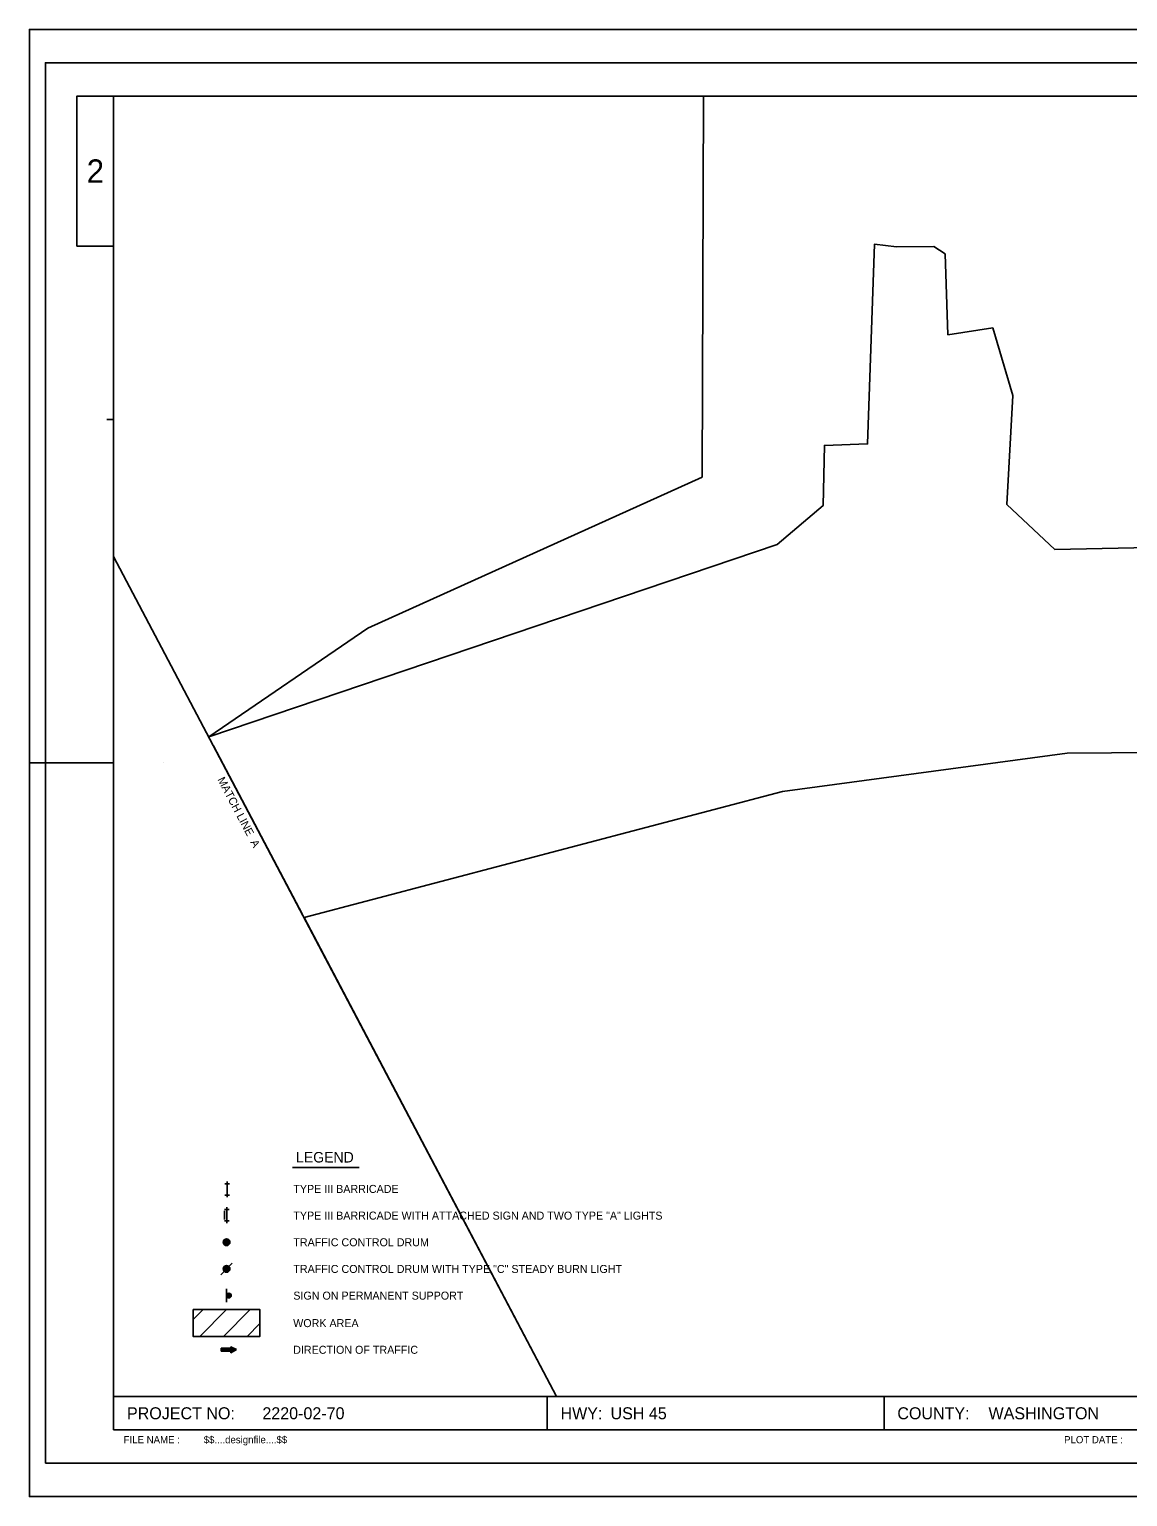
# Model space of a CAD drawing. Extents: x 359903 to 361603, y 132699 to 133799.
# Drawn here: x 359903 to 360726, y 132699 to 133799 of the extents above; entities that cross this region are included whole.
import ezdxf

# ---------------------------------------------------------------- set-up
doc = ezdxf.new("R2010")
doc.units = 0
for name, color, linetype in [('CA-MTCH-LINE', 7, 'Continuous'), ('CA-MTCH-LINE-TEXT', 7, 'Continuous'), ('Default', 7, 'Continuous'), ('P_Kapur_PFFE CELL [KAPUR_CADDS_LEVELS]', 7, 'Continuous'), ('P_RDWY_Text', 7, 'Continuous'), ('P_TC', 7, 'Continuous'), ('P_TC_FlowArrow', 7, 'Continuous'), ('P_TC_Text', 7, 'Continuous'), ('PLT_Sheet_Border', 7, 'Continuous'), ('PLT_Sheet_Info', 7, 'Continuous')]:
    doc.layers.add(name, color=color, linetype=linetype)

msp = doc.modelspace()

# ---------------------------------------------------------------- linework, layer by layer
at = {"layer": 'CA-MTCH-LINE'}
msp.add_line((360041.1, 133262.2), (360107.9, 133135.6), dxfattribs=at)
at = {"layer": 'Default'}
msp.add_lwpolyline([(361541.3, 132774.3), (360298.3, 132774.3), (359966.3, 133404.1), (359966.3, 133749.3), (361541.3, 133749.3)], close=True, dxfattribs=at)
for points in [[(361039, 133417.1), (360671.8, 133409.4), (360635.9, 133443.1), (360640.4, 133524.8), (360625.3, 133575.4), (360591.7, 133570.4), (360589.6, 133630.9), (360581.1, 133636.4), (360553.1, 133636.3), (360536.8, 133638.3), (360531.5, 133488.5), (360499.1, 133487.4), (360498.1, 133442.3), (360463.6, 133413.1), (360037.7, 133268.8), (360156.9, 133350.4), (360407.4, 133463.6), (360408.4, 133749.3), (361541.3, 133749.3)], [(361541.3, 132774.3), (360298.3, 132774.3), (360109, 133133.5), (360467.7, 133228), (360681.2, 133256.7), (361013.7, 133259.1)]]:
    msp.add_lwpolyline(points, dxfattribs=at)
at = {"layer": 'P_Kapur_PFFE CELL [KAPUR_CADDS_LEVELS]'}
msp.add_lwpolyline([(359903.1, 133799.3), (361603.1, 133799.3), (361603.1, 132699.3), (359903.1, 132699.3), (359903.1, 133799.3)], dxfattribs=at)
at = {"layer": 'P_RDWY_Text'}
msp.add_lwpolyline([(359903.1, 133799.3), (361603.1, 133799.3), (361603.1, 132699.3), (359903.1, 132699.3)], close=True, dxfattribs=at)
at = {"layer": 'P_TC'}
for p, q in [((360051.4, 132933.9), (360051.4, 132935.6)), ((360051.4, 132933.9), (360049.7, 132933.9)), ((360051.4, 132925.4), (360049.7, 132925.4)), ((360051.4, 132925.4), (360051.4, 132933.9)), ((360051.4, 132933.9), (360053.1, 132933.9)), ((360053.1, 132925.4), (360051.4, 132925.4)), ((360051.4, 132925.4), (360051.4, 132923.7)), ((360051.2, 132914.6), (360049.5, 132914.6)), ((360049.5, 132907.1), (360049.5, 132913.6)), ((360051.2, 132914.6), (360051.2, 132916.3)), ((360051.2, 132906.1), (360051.2, 132914.6)), ((360051.2, 132914.6), (360052.9, 132914.6)), ((360051.2, 132906.1), (360049.5, 132906.1)), ((360052.9, 132906.1), (360051.2, 132906.1)), ((360051.2, 132906.1), (360051.2, 132904.4)), ((360046.7, 132865.7), (360055.2, 132874.3)), ((360051, 132845), (360051, 132855)), ((360025.9, 132832.2), (360033.3, 132839.5)), ((360030.9, 132819.4), (360051, 132839.5)), ((360048.6, 132819.4), (360068.6, 132839.5)), ((360066.3, 132819.4), (360075.9, 132829.1))]:
    msp.add_line(p, q, dxfattribs=at)
msp.add_lwpolyline([(360025.9, 132839.5), (360075.9, 132839.5), (360075.9, 132819.4), (360025.9, 132819.4)], close=True, dxfattribs=at)
for centre, radius in [((360051, 132890), 2.5), ((360051, 132890), 2), ((360051, 132890), 1.5), ((360051, 132890), 1), ((360051, 132890), 0.5), ((360051, 132890), 0.25), ((360051, 132870), 2.5), ((360051, 132870), 2), ((360051, 132870), 1.5), ((360051, 132870), 1), ((360051, 132870), 0.5), ((360051, 132870), 0.25), ((360052.7, 132850), 1.75), ((360052.7, 132850), 1), ((360052.7, 132850), 0.25)]:
    msp.add_circle(centre, radius, dxfattribs=at)
at = {"layer": 'P_TC_FlowArrow'}
for p, q in [((360046.9, 132810.5), (360046.9, 132808.3)), ((360046.9, 132810.5), (360054.1, 132810.5)), ((360046.9, 132810.1), (360057.2, 132810.1)), ((360046.9, 132809.6), (360058.1, 132809.6)), ((360046.9, 132809.4), (360046.9, 132809.4)), ((360046.9, 132809.2), (360057.9, 132809.2)), ((360046.9, 132808.7), (360057.1, 132808.7)), ((360046.9, 132808.3), (360054.1, 132808.3)), ((360058.4, 132809.5), (360054.1, 132811.7)), ((360054.1, 132811.7), (360054.1, 132807.2)), ((360054.1, 132811.4), (360054.5, 132811.4)), ((360054.1, 132811), (360055.4, 132811)), ((360054.1, 132810.5), (360056.3, 132810.5)), ((360058.4, 132809.5), (360054.1, 132807.2)), ((360054.1, 132808.3), (360056.2, 132808.3)), ((360054.1, 132807.8), (360055.4, 132807.8)), ((360054.1, 132807.4), (360054.5, 132807.4))]:
    msp.add_line(p, q, dxfattribs=at)
at = {"layer": 'P_TC_Text'}
msp.add_line((360100.4, 132946.1), (360150.3, 132946.1), dxfattribs=at)
at = {"layer": 'PLT_Sheet_Border'}
for points in [[(359903.1, 132699.3), (361603.1, 132699.3), (361603.1, 133799.3), (359903.1, 133799.3)], [(359915.1, 132724.3), (361570.1, 132724.3), (361570.1, 133774.3), (359915.1, 133774.3)]]:
    msp.add_lwpolyline(points, close=True, dxfattribs=at)
at = {"layer": 'PLT_Sheet_Info'}
for p, q in [((359903.1, 133749.3), (359903.1, 133799.3)), ((359903.1, 133799.3), (359953.1, 133799.3)), ((359966.3, 133749.3), (361541.3, 133749.3)), ((359966.3, 132749.3), (359966.3, 133749.3)), ((359966.3, 133506.8), (359961.3, 133506.8)), ((359903.1, 133224.3), (359903.1, 133274.3)), ((359903.1, 133249.3), (359966.3, 133249.3)), ((360003.8, 133249.3), (360003.8, 133249.3)), ((359966.3, 132774.3), (361541.3, 132774.3)), ((360291.3, 132749.3), (360291.3, 132774.3)), ((360543.8, 132749.3), (360543.8, 132774.3)), ((359903.1, 132699.3), (359903.1, 132749.3)), ((359966.3, 132749.3), (361541.3, 132749.3)), ((359903.1, 132699.3), (359953.1, 132699.3))]:
    msp.add_line(p, q, dxfattribs=at)
msp.add_lwpolyline([(359966.3, 133749.3), (359938.8, 133749.3), (359938.8, 133636.8), (359966.3, 133636.8)], close=True, dxfattribs=at)

# ---------------------------------------------------------------- texts
at = {"layer": 'CA-MTCH-LINE-TEXT'}
msp.add_text('MATCH LINE  A', height=6, rotation=297.713, dxfattribs=at).set_placement((360043.9, 133236.9))
at = {"layer": 'P_TC_Text'}
for s, height, p in [('LEGEND', 7.88, (360103, 132949.8)), ('TYPE III BARRICADE', 6, (360101, 132927)), ('TYPE III BARRICADE WITH ATTACHED SIGN AND TWO TYPE "A" LIGHTS', 6, (360101, 132907)), ('TRAFFIC CONTROL DRUM', 6, (360101, 132887)), ('TRAFFIC CONTROL DRUM WITH TYPE "C" STEADY BURN LIGHT', 6, (360101, 132867)), ('SIGN ON PERMANENT SUPPORT', 6, (360101, 132847)), ('WORK AREA', 6, (360100.9, 132826.4)), ('DIRECTION OF TRAFFIC', 6, (360100.9, 132806.4))]:
    msp.add_text(s, height=height, rotation=359.9953, dxfattribs=at).set_placement(p)
at = {"layer": 'PLT_Sheet_Info'}
for s, height, p in [('2', 17.5, (359946.1, 133684.3)), ('PROJECT NO:', 9, (359976.3, 132757.3)), ('2220-02-70 ', 9, (360077.8, 132757.3)), ('HWY:', 9, (360301.3, 132757.3)), ('USH 45', 9, (360338.8, 132757.3)), ('COUNTY:', 9, (360553.8, 132757.3)), (' WASHINGTON', 9, (360618.8, 132757.3)), ('FILE NAME :', 5.4, (359973.8, 132739.3))]:
    msp.add_text(s, height=height, dxfattribs=at).set_placement(p)
for s, p in [('$$....designfile....$$', (360033.8, 132739.3)), ('PLOT DATE :', (360678.8, 132739.3))]:
    msp.add_text(s, height=5.4, rotation=360, dxfattribs=at).set_placement(p)

doc.saveas('drawing.dxf')
